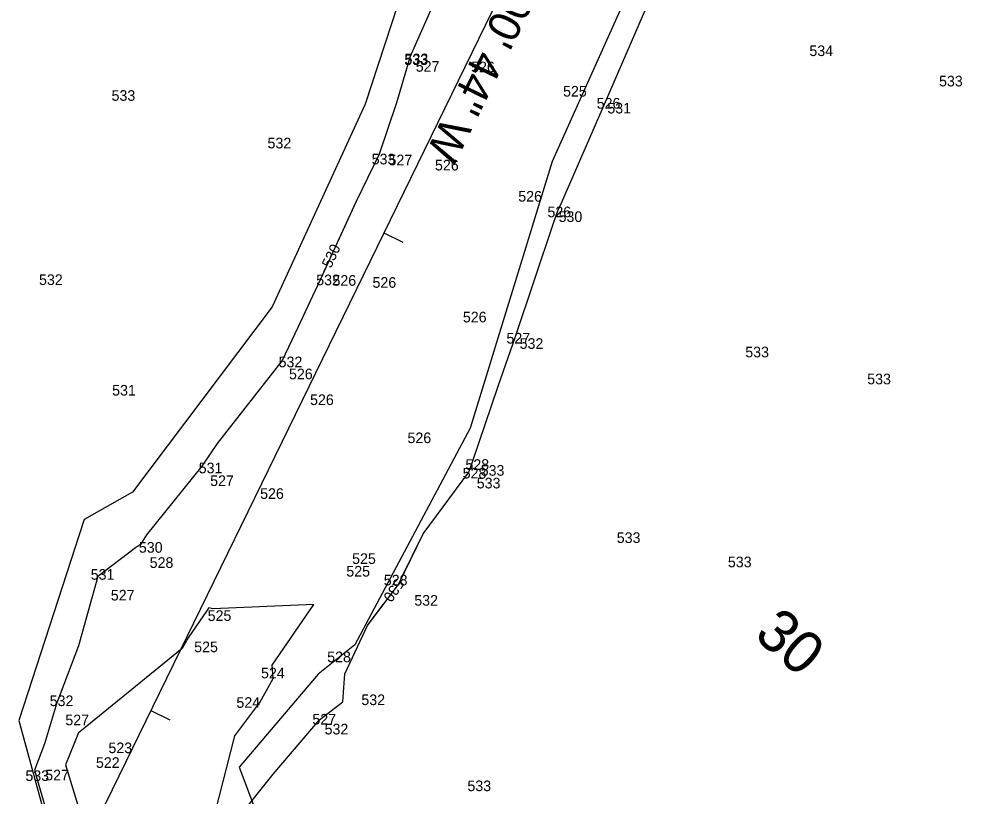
# Model space of a CAD drawing. Extents: x 1787461 to 1970323, y 938412 to 1118748.
# Drawn here: x 1967713.8 to 1967891.3, y 1117568.5 to 1117714.7 of the extents above; entities that cross this region are included whole.
import ezdxf

# ---------------------------------------------------------------- set-up
doc = ezdxf.new("R2010")
doc.units = 0
for name, color, linetype in [('Default', 7, 'Continuous'), ('RD_EX_DV_Prop', 7, 'Continuous'), ('RD_EX_H2O', 7, 'Continuous'), ('RD_HC_CL', 7, 'Continuous'), ('RD_HC_Data', 7, 'Continuous'), ('RD_HC_Data_Tic', 7, 'Continuous'), ('RD_HC_TX_Sta50', 7, 'Continuous')]:
    doc.layers.add(name, color=color, linetype=linetype)

msp = doc.modelspace()

# ---------------------------------------------------------------- linework, layer by layer
at = {"layer": 'Default'}
for points in [[(1967785.77, 1117609.46), (1967789.86, 1117617.86), (1967798.49, 1117629.43), (1967798.85, 1117630.5), (1967799.16, 1117631.38), (1967803.98, 1117645.6), (1967807.24, 1117654.97), (1967814.41, 1117676.3), (1967815.2, 1117678.59), (1967815.94, 1117680.25), (1967824.16, 1117699.1), (1967831.36, 1117715.62), (1967834.2, 1117721.99), (1967836.61, 1117725.9), (1967842.06, 1117734.92), (1967847.86, 1117744.33), (1967854.99, 1117756.1), (1967856.74, 1117762.12), (1967858.55, 1117767.59), (1967862.58, 1117781.44), (1967865.81, 1117791.38), (1967865.83, 1117791.44)], [(1967785.77, 1117609.46), (1967789.86, 1117617.86), (1967798.49, 1117629.43), (1967798.85, 1117630.5), (1967799.16, 1117631.38), (1967803.98, 1117645.6), (1967807.24, 1117654.97), (1967814.41, 1117676.3), (1967815.2, 1117678.59), (1967815.94, 1117680.25), (1967824.16, 1117699.1), (1967831.36, 1117715.62), (1967834.2, 1117721.99), (1967836.61, 1117725.9), (1967842.06, 1117734.92), (1967847.86, 1117744.33), (1967854.99, 1117756.1), (1967856.74, 1117762.12), (1967858.55, 1117767.59), (1967862.58, 1117781.44), (1967865.81, 1117791.38), (1967865.83, 1117791.44)], [(1967785.77, 1117609.46), (1967789.86, 1117617.86), (1967798.49, 1117629.43), (1967798.85, 1117630.5), (1967799.16, 1117631.38), (1967803.98, 1117645.6), (1967807.24, 1117654.97), (1967814.41, 1117676.3), (1967815.2, 1117678.59), (1967815.94, 1117680.25), (1967824.16, 1117699.1), (1967831.36, 1117715.62), (1967834.2, 1117721.99), (1967836.61, 1117725.9), (1967842.06, 1117734.92), (1967847.86, 1117744.33), (1967854.99, 1117756.1), (1967856.74, 1117762.12), (1967858.55, 1117767.59), (1967862.58, 1117781.44), (1967865.81, 1117791.38), (1967865.83, 1117791.44)], [(1967785.77, 1117609.46), (1967789.86, 1117617.86), (1967798.49, 1117629.43), (1967798.85, 1117630.5), (1967799.16, 1117631.38), (1967803.98, 1117645.6), (1967807.24, 1117654.97), (1967814.41, 1117676.3), (1967815.2, 1117678.59), (1967815.94, 1117680.25), (1967824.16, 1117699.1), (1967831.36, 1117715.62), (1967834.2, 1117721.99), (1967836.61, 1117725.9), (1967842.06, 1117734.92), (1967847.86, 1117744.33), (1967854.99, 1117756.1), (1967856.74, 1117762.12), (1967858.55, 1117767.59), (1967862.58, 1117781.44), (1967865.81, 1117791.38), (1967865.83, 1117791.44)], [(1967785.77, 1117609.46), (1967789.86, 1117617.86), (1967798.49, 1117629.43), (1967798.85, 1117630.5), (1967799.16, 1117631.38), (1967803.98, 1117645.6), (1967807.24, 1117654.97), (1967814.41, 1117676.3), (1967815.2, 1117678.59), (1967815.94, 1117680.25), (1967824.16, 1117699.1), (1967831.36, 1117715.62), (1967834.2, 1117721.99), (1967836.61, 1117725.9), (1967842.06, 1117734.92), (1967847.86, 1117744.33), (1967854.99, 1117756.1), (1967856.74, 1117762.12), (1967858.55, 1117767.59), (1967862.58, 1117781.44), (1967865.81, 1117791.38), (1967865.83, 1117791.44)], [(1967785.77, 1117609.46), (1967789.86, 1117617.86), (1967798.49, 1117629.43), (1967798.85, 1117630.5), (1967799.16, 1117631.38), (1967803.98, 1117645.6), (1967807.24, 1117654.97), (1967814.41, 1117676.3), (1967815.2, 1117678.59), (1967815.94, 1117680.25), (1967824.16, 1117699.1), (1967831.36, 1117715.62), (1967834.2, 1117721.99), (1967836.61, 1117725.9), (1967842.06, 1117734.92), (1967847.86, 1117744.33), (1967854.99, 1117756.1), (1967856.74, 1117762.12), (1967858.55, 1117767.59), (1967862.58, 1117781.44), (1967865.81, 1117791.38), (1967865.83, 1117791.44)], [(1967792.24, 1117718.65), (1967787.4, 1117707.51), (1967787.37, 1117707.43), (1967784.89, 1117698.92), (1967781.6, 1117689.27), (1967777.24, 1117680.23), (1967770.91, 1117666.58), (1967766.29, 1117656.64), (1967763.32, 1117650.45), (1967751.11, 1117634.84), (1967748.24, 1117630.58), (1967737.85, 1117617.66), (1967736.72, 1117615.83), (1967735.76, 1117615.23), (1967728.69, 1117609.8), (1967725.03, 1117596.81), (1967720.87, 1117585.9), (1967718.61, 1117578.34), (1967716.75, 1117573.41), (1967720.15, 1117561.67)], [(1967792.24, 1117718.65), (1967787.4, 1117707.51), (1967787.37, 1117707.43), (1967784.89, 1117698.92), (1967781.6, 1117689.27), (1967777.24, 1117680.23), (1967773.97, 1117673.18)], [(1967792.24, 1117718.65), (1967787.4, 1117707.51), (1967787.37, 1117707.43), (1967784.89, 1117698.92), (1967781.6, 1117689.27), (1967777.24, 1117680.23), (1967773.97, 1117673.18)], [(1967792.24, 1117718.65), (1967787.4, 1117707.51), (1967787.37, 1117707.43), (1967784.89, 1117698.92), (1967781.6, 1117689.27), (1967777.24, 1117680.23), (1967773.97, 1117673.18)], [(1967792.24, 1117718.65), (1967787.4, 1117707.51), (1967787.37, 1117707.43), (1967784.89, 1117698.92), (1967781.6, 1117689.27), (1967777.24, 1117680.23), (1967773.97, 1117673.18)], [(1967792.24, 1117718.65), (1967787.4, 1117707.51), (1967787.37, 1117707.43), (1967784.89, 1117698.92), (1967781.6, 1117689.27), (1967777.24, 1117680.23), (1967773.97, 1117673.18)], [(1967792.24, 1117718.65), (1967787.4, 1117707.51), (1967787.37, 1117707.43), (1967784.89, 1117698.92), (1967781.6, 1117689.27), (1967777.24, 1117680.23), (1967773.97, 1117673.18)], [(1967755.44, 1117564.85), (1967761.67, 1117572.63), (1967770.37, 1117582.88), (1967774.78, 1117586.25), (1967775.16, 1117591.5), (1967779.38, 1117600.6), (1967785.21, 1117608.32), (1967789.86, 1117617.86), (1967798.49, 1117629.43), (1967798.85, 1117630.5), (1967799.16, 1117631.38), (1967803.98, 1117645.6), (1967807.24, 1117654.97), (1967814.41, 1117676.3), (1967815.2, 1117678.59), (1967815.94, 1117680.25), (1967824.16, 1117699.1), (1967831.36, 1117715.62)], [(1967771.44, 1117667.74), (1967770.91, 1117666.58), (1967766.29, 1117656.64), (1967763.32, 1117650.45), (1967751.11, 1117634.84), (1967748.24, 1117630.58), (1967737.85, 1117617.66), (1967736.72, 1117615.83), (1967735.76, 1117615.23), (1967728.69, 1117609.8), (1967725.03, 1117596.81), (1967720.87, 1117585.9), (1967718.61, 1117578.34), (1967716.75, 1117573.41), (1967720.15, 1117561.67), (1967723.91, 1117549.41), (1967727.02, 1117538.75), (1967731.11, 1117525.43), (1967732.54, 1117520.76), (1967733.88, 1117516.2), (1967741.13, 1117508.75), (1967753.13, 1117500.33), (1967755.97, 1117497.44)], [(1967771.44, 1117667.74), (1967770.91, 1117666.58), (1967766.29, 1117656.64), (1967763.32, 1117650.45), (1967751.11, 1117634.84), (1967748.24, 1117630.58), (1967737.85, 1117617.66), (1967736.72, 1117615.83), (1967735.76, 1117615.23), (1967728.69, 1117609.8), (1967725.03, 1117596.81), (1967720.87, 1117585.9), (1967718.61, 1117578.34), (1967716.75, 1117573.41), (1967720.15, 1117561.67), (1967723.91, 1117549.41), (1967727.02, 1117538.75), (1967731.11, 1117525.43), (1967732.54, 1117520.76), (1967733.88, 1117516.2), (1967741.13, 1117508.75), (1967753.13, 1117500.33), (1967755.97, 1117497.44)], [(1967771.44, 1117667.74), (1967770.91, 1117666.58), (1967766.29, 1117656.64), (1967763.32, 1117650.45), (1967751.11, 1117634.84), (1967748.24, 1117630.58), (1967737.85, 1117617.66), (1967736.72, 1117615.83), (1967735.76, 1117615.23), (1967728.69, 1117609.8), (1967725.03, 1117596.81), (1967720.87, 1117585.9), (1967718.61, 1117578.34), (1967716.75, 1117573.41), (1967720.15, 1117561.67), (1967723.91, 1117549.41), (1967727.02, 1117538.75), (1967731.11, 1117525.43), (1967732.54, 1117520.76), (1967733.88, 1117516.2), (1967741.13, 1117508.75), (1967753.13, 1117500.33), (1967755.97, 1117497.44)], [(1967771.44, 1117667.74), (1967770.91, 1117666.58), (1967766.29, 1117656.64), (1967763.32, 1117650.45), (1967751.11, 1117634.84), (1967748.24, 1117630.58), (1967737.85, 1117617.66), (1967736.72, 1117615.83), (1967735.76, 1117615.23), (1967728.69, 1117609.8), (1967725.03, 1117596.81), (1967720.87, 1117585.9), (1967718.61, 1117578.34), (1967716.75, 1117573.41), (1967720.15, 1117561.67), (1967723.91, 1117549.41), (1967727.02, 1117538.75), (1967731.11, 1117525.43), (1967732.54, 1117520.76), (1967733.88, 1117516.2), (1967741.13, 1117508.75), (1967753.13, 1117500.33), (1967755.97, 1117497.44)], [(1967771.44, 1117667.74), (1967770.91, 1117666.58), (1967766.29, 1117656.64), (1967763.32, 1117650.45), (1967751.11, 1117634.84), (1967748.24, 1117630.58), (1967737.85, 1117617.66), (1967736.72, 1117615.83), (1967735.76, 1117615.23), (1967728.69, 1117609.8), (1967725.03, 1117596.81), (1967720.87, 1117585.9), (1967718.61, 1117578.34), (1967716.75, 1117573.41), (1967720.15, 1117561.67), (1967723.91, 1117549.41), (1967727.02, 1117538.75), (1967731.11, 1117525.43), (1967732.54, 1117520.76), (1967733.88, 1117516.2), (1967741.13, 1117508.75), (1967753.13, 1117500.33), (1967755.97, 1117497.44)], [(1967771.44, 1117667.74), (1967770.91, 1117666.58), (1967766.29, 1117656.64), (1967763.32, 1117650.45), (1967751.11, 1117634.84), (1967748.24, 1117630.58), (1967737.85, 1117617.66), (1967736.72, 1117615.83), (1967735.76, 1117615.23), (1967728.69, 1117609.8), (1967725.03, 1117596.81), (1967720.87, 1117585.9), (1967718.61, 1117578.34), (1967716.75, 1117573.41), (1967720.15, 1117561.67), (1967723.91, 1117549.41), (1967727.02, 1117538.75), (1967731.11, 1117525.43), (1967732.54, 1117520.76), (1967733.88, 1117516.2), (1967741.13, 1117508.75), (1967753.13, 1117500.33), (1967755.97, 1117497.44)], [(1967750.76, 1117565.39), (1967754.46, 1117579.87), (1967759.16, 1117586.14), (1967761.64, 1117590.62), (1967761.47, 1117593.17), (1967769.33, 1117604.54), (1967750.28, 1117603.76), (1967749.53, 1117603.93), (1967749.33, 1117603.63), (1967749.28, 1117603.5), (1967749.22, 1117603.48), (1967745.64, 1117598.3), (1967744.56, 1117596.31), (1967726.28, 1117581.42), (1967725.02, 1117580.39), (1967722.57, 1117574.41), (1967726.98, 1117560.01)], [(1967750.76, 1117565.39), (1967754.46, 1117579.87), (1967759.16, 1117586.14), (1967761.64, 1117590.62), (1967761.47, 1117593.17), (1967769.33, 1117604.54), (1967750.28, 1117603.76), (1967749.53, 1117603.93), (1967749.33, 1117603.63), (1967749.28, 1117603.5), (1967749.22, 1117603.48), (1967745.64, 1117598.3), (1967744.56, 1117596.31), (1967726.28, 1117581.42), (1967725.02, 1117580.39), (1967722.57, 1117574.41), (1967726.98, 1117560.01)], [(1967750.76, 1117565.39), (1967754.46, 1117579.87), (1967759.16, 1117586.14), (1967761.64, 1117590.62), (1967761.47, 1117593.17), (1967769.33, 1117604.54), (1967750.28, 1117603.76), (1967749.53, 1117603.93), (1967749.33, 1117603.63), (1967749.28, 1117603.5), (1967749.22, 1117603.48), (1967745.64, 1117598.3), (1967744.56, 1117596.31), (1967726.28, 1117581.42), (1967725.02, 1117580.39), (1967722.57, 1117574.41), (1967726.98, 1117560.01)], [(1967750.76, 1117565.39), (1967754.46, 1117579.87), (1967759.16, 1117586.14), (1967761.64, 1117590.62), (1967761.47, 1117593.17), (1967769.33, 1117604.54), (1967750.28, 1117603.76), (1967749.53, 1117603.93), (1967749.33, 1117603.63), (1967749.28, 1117603.5), (1967749.22, 1117603.48), (1967745.64, 1117598.3), (1967744.56, 1117596.31), (1967726.28, 1117581.42), (1967725.02, 1117580.39), (1967722.57, 1117574.41), (1967726.98, 1117560.01)], [(1967750.76, 1117565.39), (1967754.46, 1117579.87), (1967759.16, 1117586.14), (1967761.64, 1117590.62), (1967761.47, 1117593.17), (1967769.33, 1117604.54), (1967750.28, 1117603.76), (1967749.53, 1117603.93), (1967749.33, 1117603.63), (1967749.28, 1117603.5), (1967749.22, 1117603.48), (1967745.64, 1117598.3), (1967744.56, 1117596.31), (1967726.28, 1117581.42), (1967725.02, 1117580.39), (1967722.57, 1117574.41), (1967726.98, 1117560.01)], [(1967750.76, 1117565.39), (1967754.46, 1117579.87), (1967759.16, 1117586.14), (1967761.64, 1117590.62), (1967761.47, 1117593.17), (1967769.33, 1117604.54), (1967750.28, 1117603.76), (1967749.53, 1117603.93), (1967749.33, 1117603.63), (1967749.28, 1117603.5), (1967749.22, 1117603.48), (1967745.64, 1117598.3), (1967744.56, 1117596.31), (1967726.28, 1117581.42), (1967725.02, 1117580.39), (1967722.57, 1117574.41), (1967726.98, 1117560.01)], [(1967750.76, 1117565.39), (1967754.46, 1117579.87), (1967759.16, 1117586.14), (1967761.64, 1117590.62), (1967761.47, 1117593.17), (1967769.33, 1117604.54), (1967750.28, 1117603.76), (1967749.53, 1117603.93), (1967749.33, 1117603.63), (1967749.28, 1117603.5), (1967749.22, 1117603.48), (1967745.64, 1117598.3), (1967744.56, 1117596.31), (1967726.28, 1117581.42), (1967725.02, 1117580.39), (1967722.57, 1117574.41), (1967726.98, 1117560.01)], [(1967755.44, 1117564.85), (1967761.67, 1117572.63), (1967770.37, 1117582.88), (1967774.78, 1117586.25), (1967775.16, 1117591.5), (1967779.38, 1117600.6), (1967782.36, 1117604.54)], [(1967755.44, 1117564.85), (1967761.67, 1117572.63), (1967770.37, 1117582.88), (1967774.78, 1117586.25), (1967775.16, 1117591.5), (1967779.38, 1117600.6), (1967782.36, 1117604.54)], [(1967755.44, 1117564.85), (1967761.67, 1117572.63), (1967770.37, 1117582.88), (1967774.78, 1117586.25), (1967775.16, 1117591.5), (1967779.38, 1117600.6), (1967782.36, 1117604.54)], [(1967755.44, 1117564.85), (1967761.67, 1117572.63), (1967770.37, 1117582.88), (1967774.78, 1117586.25), (1967775.16, 1117591.5), (1967779.38, 1117600.6), (1967782.36, 1117604.54)], [(1967755.44, 1117564.85), (1967761.67, 1117572.63), (1967770.37, 1117582.88), (1967774.78, 1117586.25), (1967775.16, 1117591.5), (1967779.38, 1117600.6), (1967782.36, 1117604.54)], [(1967755.44, 1117564.85), (1967761.67, 1117572.63), (1967770.37, 1117582.88), (1967774.78, 1117586.25), (1967775.16, 1117591.5), (1967779.38, 1117600.6), (1967782.36, 1117604.54)]]:
    msp.add_lwpolyline(points, dxfattribs=at)
at = {"layer": 'RD_EX_DV_Prop'}
msp.add_line((1967848.59, 1117809.96), (1967728.08, 1117563.01), dxfattribs=at)
at = {"layer": 'RD_EX_H2O'}
for points in [[(1967793.07, 1117884.81), (1967795.4, 1117862.79), (1967808.44, 1117844.76), (1967827.6, 1117817.64), (1967803.85, 1117763.92), (1967785.1, 1117717.4), (1967778.96, 1117698.7), (1967761.45, 1117660.55), (1967735.16, 1117625.66), (1967726.1, 1117620.57), (1967713.81, 1117582.71), (1967729.78, 1117524.09), (1967774.63, 1117477.47), (1967792.06, 1117468.24), (1967815.16, 1117463.54)], [(1967872.32, 1117822.66), (1967872.31, 1117820.09), (1967867.75, 1117800.84), (1967855.06, 1117765.41), (1967833.55, 1117731.08), (1967814.13, 1117687.88), (1967798.73, 1117637.75), (1967777.02, 1117596.99), (1967770.1, 1117591.47), (1967755.23, 1117573.96), (1967763.13, 1117553.21), (1967794.74, 1117526.69), (1967804.69, 1117522.56), (1967827.72, 1117512.92)]]:
    msp.add_lwpolyline(points, dxfattribs=at)
at = {"layer": 'RD_HC_CL'}
msp.add_line((1967848.59, 1117809.96), (1967728.08, 1117563.01), dxfattribs=at)
at = {"layer": 'RD_HC_Data_Tic'}
for p, q in [((1967782.47, 1117674.47), (1967786.06, 1117672.72)), ((1967738.61, 1117584.6), (1967742.21, 1117582.85))]:
    msp.add_line(p, q, dxfattribs=at)

# ---------------------------------------------------------------- texts
at = {"layer": 'Default'}
for s, p in [('534', (1967862.54, 1117707.73)), ('533', (1967786.33, 1117706.04)), ('533', (1967786.39, 1117706.19)), ('527', (1967788.48, 1117704.78)), ('526', (1967798.9, 1117704.68)), ('533', (1967886.94, 1117702.02)), ('533', (1967731.25, 1117699.31)), ('525', (1967816.2, 1117700.11)), ('526', (1967822.52, 1117697.84)), ('531', (1967824.53, 1117696.93)), ('532', (1967760.59, 1117690.36)), ('533', (1967780.19, 1117687.35)), ('527', (1967783.36, 1117687.17)), ('526', (1967792.1, 1117686.21)), ('526', (1967807.77, 1117680.35)), ('526', (1967813.26, 1117677.41)), ('530', (1967815.36, 1117676.52)), ('532', (1967717.6, 1117664.66)), ('532', (1967769.76, 1117664.62)), ('526', (1967772.81, 1117664.52)), ('526', (1967780.35, 1117664.14)), ('526', (1967797.35, 1117657.63)), ('527', (1967805.55, 1117653.65)), ('532', (1967808.03, 1117652.65)), ('533', (1967850.48, 1117651.05)), ('532', (1967762.68, 1117649.19)), ('526', (1967764.63, 1117646.93)), ('533', (1967873.42, 1117645.98)), ('531', (1967731.36, 1117643.86)), ('526', (1967768.6, 1117642.08)), ('526', (1967786.93, 1117634.91)), ('528', (1967797.83, 1117629.89)), ('531', (1967747.65, 1117629.24)), ('528', (1967797.31, 1117628.26)), ('533', (1967800.7, 1117628.78)), ('527', (1967749.8, 1117626.85)), ('533', (1967799.96, 1117626.39)), ('526', (1967759.2, 1117624.42)), ('533', (1967826.3, 1117616.13)), ('530', (1967736.39, 1117614.3)), ('525', (1967776.51, 1117612.18)), ('528', (1967738.42, 1117611.44)), ('533', (1967847.21, 1117611.56)), ('531', (1967727.33, 1117609.21)), ('525', (1967775.42, 1117609.81)), ('528', (1967782.47, 1117608.14)), ('527', (1967731.11, 1117605.31)), ('532', (1967788.21, 1117604.33)), ('525', (1967749.33, 1117601.46)), ('525', (1967746.8, 1117595.58)), ('528', (1967771.82, 1117593.7)), ('524', (1967759.37, 1117590.66)), ('532', (1967719.61, 1117585.44)), ('524', (1967754.74, 1117585.12)), ('532', (1967778.25, 1117585.63)), ('527', (1967722.55, 1117581.83)), ('527', (1967769.03, 1117581.97)), ('532', (1967771.33, 1117580.11)), ('523', (1967730.66, 1117576.59)), ('522', (1967728.31, 1117573.82)), ('533', (1967715.04, 1117571.35)), ('527', (1967718.77, 1117571.47)), ('533', (1967798.2, 1117569.44))]:
    msp.add_text(s, height=2, dxfattribs=at).set_placement(p)
for rotation, p in [(65.0819, (1967772.53, 1117667.7)), (65.0819, (1967772.53, 1117667.7)), (65.0819, (1967772.53, 1117667.7)), (65.0819, (1967772.53, 1117667.7)), (65.0819, (1967772.53, 1117667.7)), (65.0819, (1967772.53, 1117667.7)), (235.2411, (1967784.81, 1117609.62)), (235.2411, (1967784.81, 1117609.62)), (235.2411, (1967784.81, 1117609.62)), (235.2411, (1967784.81, 1117609.62)), (235.2411, (1967784.81, 1117609.62)), (235.2411, (1967784.81, 1117609.62))]:
    msp.add_text('530', height=2, rotation=rotation, dxfattribs=at).set_placement(p)
at = {"layer": 'RD_HC_Data'}
msp.add_text('S 26%%d 00\' 44" W', height=6, rotation=243.9877, dxfattribs=at).set_placement((1967815.06, 1117740.34))
at = {"layer": 'RD_HC_TX_Sta50'}
msp.add_text('30', height=8, rotation=318.9993, dxfattribs=at).set_placement((1967851.9, 1117598.48))

doc.saveas('drawing.dxf')
